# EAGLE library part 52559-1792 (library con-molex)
FFC/FPC-to-Board 0.50mm (.020") SMT, Vertical, ZIF Receptacle Source: http://www.molex.com/product/ffc/52559.html
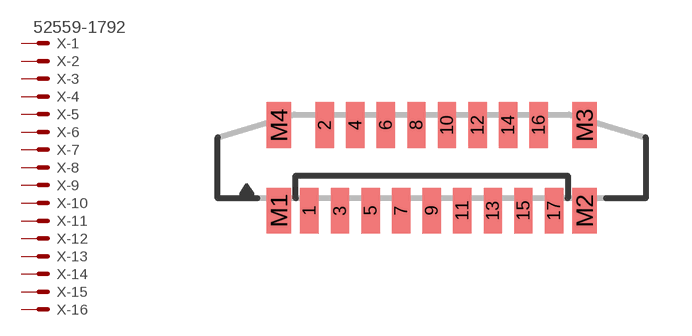
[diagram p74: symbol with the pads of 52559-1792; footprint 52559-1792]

Designator prefix X; gates -1=MV -2=M -3=M -4=M -5=M -6=M -7=M -8=M -9=M -10=M -11=M -12=M -13=M -14=M -15=M -16=M -17=M

## 52559-1792 (OC_FARNELL: unknown; OC_NEWARK: unknown)  [52559-1792]
1  -1:S  pas
2  -2:S  pas
3  -3:S  pas
4  -4:S  pas
5  -5:S  pas
6  -6:S  pas
7  -7:S  pas
8  -8:S  pas
9  -9:S  pas
10  -10:S  pas
11  -11:S  pas
12  -12:S  pas
13  -13:S  pas
14  -14:S  pas
15  -15:S  pas
16  -16:S  pas
17  -17:S  pas

## Footprint 52559-1792 (pad centres in mm)
FFC/FPC-to-Board 0.50mm (.020") SMT, Vertical, ZIF Receptacle Source: http://www.molex.com/product/ffc/52559.html
smd 0.6 x 1.5: 1 -4,-1.4; 2 -3.5,1.4; 3 -3,-1.4; 4 -2.5,1.4; 5 -2,-1.4; 6 -1.5,1.4; 7 -1,-1.4; 8 -0.5,1.4; 9 0,-1.4; 10 0.5,1.4; 11 1,-1.4; 12 1.5,1.4; 13 2,-1.4; 14 2.5,1.4; 15 3,-1.4; 16 3.5,1.4; 17 4,-1.4
smd 0.8 x 1.5: M1 -5,-1.4; M2 5,-1.4; M3 5,1.4; M4 -5,1.4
